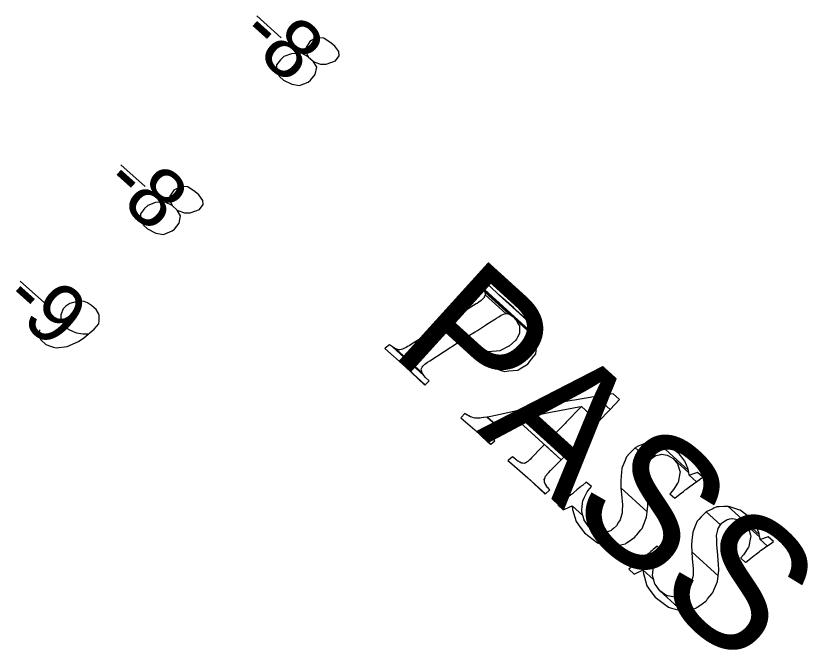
# Model space of a CAD drawing. Extents: x 3962991 to 3983549, y 181631 to 204078.
# Drawn here: x 3976572.4 to 3977019.6, y 191060.4 to 191418 of the extents above; entities that cross this region are included whole.
import ezdxf

# ---------------------------------------------------------------- set-up
doc = ezdxf.new("R2010")
doc.units = 0
for name, color, linetype in [('V-ANNO-MASK', 7, 'Continuous'), ('V-ANNO-MASK2', 7, 'Continuous'), ('V-RIVR-IDEN', 7, 'Continuous'), ('V-RIVR-RANG', 7, 'Continuous')]:
    doc.layers.add(name, color=color, linetype=linetype)

msp = doc.modelspace()

# ---------------------------------------------------------------- linework, layer by layer
at = {"layer": 'V-ANNO-MASK2'}
for p, q in [((3976708.04, 191417.99), (3976721.79, 191405.66)), ((3976631.45, 191334.22), (3976645.2, 191321.9)), ((3976574.79, 191268.71), (3976588.54, 191256.38))]:
    msp.add_line(p, q, dxfattribs=at)
for points in [[(3976736.95, 191394.91), (3976739.7, 191392.45), (3976740.67, 191391.94), (3976743.9, 191390.81), (3976747.08, 191390.8), (3976752.39, 191392.77), (3976754.48, 191395.5), (3976754.16, 191397.91), (3976751.94, 191400.96), (3976749.98, 191402.72), (3976745.72, 191405.48), (3976743.09, 191405.71), (3976740.15, 191404.8), (3976737.97, 191403.56), (3976735.73, 191400.26), (3976735.46, 191398.38), (3976736.95, 191394.91), (3976733.11, 191396.94), (3976727.52, 191396.64), (3976723.31, 191395.1), (3976721.35, 191393.31), (3976719.08, 191390.38), (3976719.09, 191386.83), (3976720.74, 191383.94), (3976723.1, 191381.82), (3976727.71, 191379.46), (3976732.05, 191378.76), (3976736.98, 191380.72), (3976738.24, 191381.72), (3976740.86, 191385.04), (3976741.75, 191389.2), (3976739.7, 191392.45)], [(3976660.36, 191311.15), (3976663.11, 191308.68), (3976664.07, 191308.17), (3976667.31, 191307.04), (3976670.48, 191307.03), (3976675.79, 191309), (3976677.88, 191311.73), (3976677.56, 191314.14), (3976675.34, 191317.2), (3976673.38, 191318.96), (3976669.12, 191321.71), (3976666.49, 191321.94), (3976663.55, 191321.04), (3976661.38, 191319.8), (3976659.13, 191316.5), (3976658.86, 191314.61), (3976660.36, 191311.15), (3976656.51, 191313.18), (3976650.92, 191312.87), (3976646.71, 191311.33), (3976644.75, 191309.55), (3976642.48, 191306.62), (3976642.49, 191303.07), (3976644.14, 191300.17), (3976646.5, 191298.06), (3976651.11, 191295.7), (3976655.45, 191295), (3976660.39, 191296.95), (3976661.64, 191297.95), (3976664.26, 191301.27), (3976665.15, 191305.43), (3976663.11, 191308.68)], [(3976585.63, 191241.28), (3976585.27, 191237.71), (3976586.51, 191235.54), (3976589.26, 191233.07), (3976591.93, 191232.1), (3976593.46, 191231.44), (3976594.97, 191231.14), (3976601.28, 191231.86), (3976607.67, 191234.64), (3976610.54, 191236.67), (3976616.43, 191241.66), (3976619.08, 191244.61), (3976619.35, 191246.49), (3976619.18, 191249.47), (3976618.95, 191250.39), (3976617.51, 191252.74), (3976614.96, 191255.03), (3976612.64, 191256.4), (3976610.91, 191257.24), (3976607.54, 191257.42), (3976602.76, 191256.04), (3976600.41, 191254.61), (3976599, 191253.03), (3976597.69, 191249.6), (3976597.6, 191247.91), (3976598.27, 191245.9), (3976600.1, 191243.19), (3976601.87, 191241.61), (3976604.56, 191240.26), (3976606.46, 191239.62), (3976610.22, 191239.08), (3976612.28, 191239), (3976613.4, 191239.07)]]:
    msp.add_lwpolyline(points, dxfattribs=at)
for points in [[(3976834.16, 191269.19), (3976832.05, 191267.69), (3976865.53, 191237.34), (3976863.46, 191242.62), (3976859.91, 191246.85), (3976844.27, 191261.03), (3976839.3, 191265.75), (3976839.29, 191265.76), (3976835.04, 191269.8), (3976834.92, 191269.72), (3976834.79, 191269.63)], [(3976833.45, 191266.43), (3976835.18, 191264.52), (3976865.73, 191236.81), (3976865.53, 191237.34)], [(3976836.2, 191262.85), (3976836.42, 191262.5), (3976850.09, 191250.11), (3976850.32, 191250.05), (3976850.5, 191249.92), (3976850.85, 191249.67), (3976852.09, 191248.75), (3976865.99, 191236.15), (3976865.73, 191236.81), (3976835.17, 191264.52), (3976835.78, 191263.55), (3976836.07, 191263.06), (3976836.16, 191262.92)], [(3976787.99, 191229.9), (3976786.21, 191230.57), (3976801.18, 191217), (3976800.76, 191218.33), (3976800.53, 191219.06), (3976801.19, 191220.23), (3976801.19, 191220.24), (3976801.55, 191220.86), (3976802.66, 191221.88), (3976803.29, 191222.44), (3976804.05, 191222.95), (3976805.42, 191223.88), (3976821.52, 191234.35), (3976821.8, 191234.53), (3976830.47, 191226.67), (3976837.65, 191221.23), (3976846.25, 191218.24), (3976825.76, 191236.83), (3976825.87, 191236.91), (3976826.17, 191237.1), (3976827.82, 191238.15), (3976831.02, 191240.19), (3976832.2, 191240.93), (3976836.85, 191243.89), (3976836.99, 191243.98), (3976841.45, 191246.81), (3976841.91, 191247.1), (3976842.96, 191247.77), (3976844.31, 191248.63), (3976845.13, 191249.15), (3976845.67, 191249.49), (3976846.51, 191249.86), (3976846.83, 191249.99), (3976848.28, 191250.4), (3976836.65, 191260.94), (3976836.11, 191259.72), (3976835.98, 191259.41), (3976835.39, 191258.81), (3976834.96, 191258.37), (3976834.31, 191257.7), (3976833.01, 191256.79), (3976832.01, 191256.07), (3976831.54, 191255.79), (3976827.05, 191252.99), (3976826.91, 191252.9), (3976822.21, 191249.99), (3976821.02, 191249.25), (3976817.79, 191247.25), (3976816.13, 191246.21), (3976815.82, 191246.02), (3976815.7, 191245.94), (3976812.55, 191243.99), (3976811.85, 191243.55), (3976811.57, 191243.38), (3976795.17, 191233.18), (3976793.75, 191232.29), (3976792.94, 191231.82), (3976792.19, 191231.38), (3976790.74, 191230.66), (3976790.07, 191230.32), (3976788.46, 191230)], [(3976836.59, 191261.37), (3976836.66, 191260.94), (3976848.28, 191250.4), (3976848.6, 191250.48), (3976850.09, 191250.11), (3976836.41, 191262.51)], [(3976852.56, 191253.73), (3976844.27, 191261.03), (3976859.91, 191246.85), (3976859.16, 191247.75), (3976853.75, 191252.68), (3976853.74, 191252.69)], [(3976831.77, 191231.56), (3976825.76, 191236.83), (3976846.25, 191218.24), (3976846.58, 191218.13), (3976847.41, 191217.84), (3976849.96, 191218.07), (3976854.92, 191218.51), (3976856.1, 191219.26), (3976860.81, 191222.17), (3976860.9, 191222.3), (3976864.02, 191226.34), (3976864.33, 191226.76), (3976865.07, 191227.72), (3976865.32, 191229.58), (3976865.48, 191230.7), (3976865.58, 191231.43), (3976865.71, 191232.44), (3976865.77, 191232.83), (3976865.97, 191234.36), (3976866.02, 191234.68), (3976866.14, 191235.56), (3976866.16, 191235.69), (3976866.16, 191235.72), (3976866.13, 191235.81), (3976854.05, 191246.77), (3976854.12, 191246.64), (3976854.15, 191246.58), (3976854.33, 191246.26), (3976855.43, 191244.28), (3976855.85, 191243.53), (3976855.9, 191241.77), (3976855.91, 191241.33), (3976855.95, 191240.16), (3976855.98, 191239.31), (3976855.52, 191238.46), (3976854.77, 191237.06), (3976854.18, 191235.97), (3976853.93, 191235.49), (3976850.12, 191232.07), (3976849.97, 191232), (3976844.81, 191229.49), (3976843.01, 191229.32), (3976838.12, 191228.81), (3976832.74, 191231.14)], [(3976852.09, 191248.75), (3976854.05, 191246.76), (3976866.12, 191235.82), (3976865.99, 191236.15)], [(3976780.3, 191230.83), (3976780.04, 191230.64), (3976791.59, 191220.6), (3976802.87, 191210.37), (3976805.1, 191212.46), (3976803.04, 191214.48), (3976802.15, 191215.59), (3976784.39, 191231.69), (3976782.8, 191232.83), (3976782.71, 191232.75)], [(3976821.79, 191234.54), (3976827.59, 191228.84), (3976830.47, 191226.67)], [(3976785.46, 191231.03), (3976784.4, 191231.69), (3976802.15, 191215.59), (3976801.27, 191216.7), (3976801.18, 191217), (3976786.2, 191230.58)], [(3976791.59, 191220.6), (3976802.64, 191210.15), (3976802.87, 191210.37)], [(3976908.66, 191205.25), (3976898.86, 191203.67), (3976906.9, 191196.39), (3976912.3, 191201.95)], [(3976839.73, 191192.5), (3976837.77, 191192.09), (3976842.42, 191187.88), (3976844.15, 191188.49), (3976849.23, 191189.84), (3976850.14, 191190.05), (3976854.21, 191191), (3976879.41, 191168.14), (3976882.87, 191171.7), (3976860.18, 191192.27), (3976862.14, 191192.67), (3976874.34, 191195.14), (3976875.39, 191195.32), (3976889.43, 191197.84), (3976889.42, 191197.85), (3976890.79, 191198.08), (3976900.22, 191189.53), (3976906.9, 191196.39), (3976898.86, 191203.68), (3976886.84, 191201.66), (3976885.47, 191201.42), (3976871.41, 191198.93), (3976870.37, 191198.74), (3976858.05, 191196.38), (3976856.1, 191195.97), (3976850.13, 191194.69), (3976846.01, 191193.8), (3976845.07, 191193.61)], [(3976874.58, 191181.39), (3976873.46, 191180.23), (3976882.87, 191171.7), (3976883.99, 191172.86), (3976890.99, 191180.05), (3976891.58, 191180.65), (3976899.46, 191188.75), (3976900.22, 191189.53), (3976890.79, 191198.08), (3976890.02, 191197.3), (3976882.16, 191189.19), (3976881.57, 191188.59)], [(3976823.11, 191191.89), (3976822.97, 191191.74), (3976830.74, 191184.98), (3976839.74, 191176.82), (3976842.13, 191178.69), (3976841.65, 191179.23), (3976841.16, 191179.76), (3976840.58, 191180.47), (3976840.49, 191180.58), (3976840.3, 191180.82), (3976839.72, 191181.52), (3976839.65, 191181.65), (3976839.26, 191182.37), (3976839.23, 191182.43), (3976838.74, 191183.33), (3976838.72, 191183.39), (3976838.68, 191184), (3976838.65, 191184.49), (3976838.63, 191184.85), (3976838.78, 191185.11), (3976839.1, 191185.64), (3976839.42, 191186.18), (3976839.48, 191186.26), (3976839.96, 191186.62), (3976840.77, 191187.23), (3976840.9, 191187.32), (3976842.18, 191187.79), (3976842.42, 191187.88), (3976837.77, 191192.1), (3976837.48, 191192.05), (3976835.93, 191191.83), (3976835.73, 191191.8), (3976834.45, 191191.61), (3976833.69, 191191.5), (3976833.57, 191191.49), (3976832.63, 191191.51), (3976831.68, 191191.55), (3976831.22, 191191.56), (3976830.83, 191191.58), (3976830.1, 191191.78), (3976829.16, 191192.05), (3976829.11, 191192.06), (3976828.37, 191192.28), (3976828.29, 191192.31), (3976827.35, 191192.81), (3976827.19, 191192.89), (3976826.71, 191193.14), (3976826.55, 191193.22), (3976826.47, 191193.26), (3976825.8, 191193.69), (3976825.47, 191193.9), (3976825.13, 191194.11)], [(3976837.94, 191178.17), (3976839.54, 191176.65), (3976839.57, 191176.69), (3976839.74, 191176.82), (3976830.73, 191184.98)], [(3976849.43, 191167.68), (3976849.38, 191167.64), (3976851.61, 191165.71), (3976853.11, 191164.41), (3976860.59, 191157.94), (3976870.55, 191148.91), (3976872.73, 191150.95), (3976872.78, 191150.99), (3976872.83, 191151.04), (3976872.93, 191151.13), (3976872.95, 191151.14), (3976872.66, 191151.47), (3976871.81, 191152.43), (3976871.52, 191152.75), (3976870.94, 191153.64), (3976870.89, 191153.72), (3976870.17, 191154.84), (3976870.16, 191154.88), (3976870.06, 191155.55), (3976869.99, 191156.07), (3976869.93, 191156.46), (3976869.87, 191156.91), (3976870.12, 191157.52), (3976870.36, 191158.13), (3976870.4, 191158.22), (3976870.63, 191158.8), (3976871.26, 191159.58), (3976871.25, 191159.59), (3976871.36, 191159.71), (3976872.12, 191160.64), (3976872.27, 191160.81), (3976873.4, 191161.97), (3976876.48, 191165.13), (3976877.01, 191165.69), (3976879.41, 191168.14), (3976870, 191176.68), (3976867.6, 191174.22), (3976867.07, 191173.66), (3976863.99, 191170.5), (3976862.86, 191169.35), (3976862.71, 191169.18), (3976861.87, 191168.32), (3976861.76, 191168.2), (3976861.01, 191167.53), (3976860.57, 191167.13), (3976860.5, 191167.07), (3976860.05, 191166.65), (3976859.42, 191166.39), (3976859.12, 191166.27), (3976858.87, 191166.16), (3976858.52, 191166.01), (3976857.75, 191166.13), (3976857.71, 191166.13), (3976857.1, 191166.22), (3976857.06, 191166.23), (3976856.12, 191166.72), (3976855.96, 191166.8), (3976855.49, 191167.04), (3976855.18, 191167.26), (3976855.02, 191167.38), (3976854.07, 191168.05), (3976853.61, 191168.38), (3976852.08, 191169.67), (3976849.65, 191167.86), (3976849.47, 191167.72)], [(3976912.95, 191155.99), (3976913.02, 191152.33), (3976927.87, 191138.87), (3976928.26, 191142.1), (3976928.26, 191142.38), (3976928.25, 191142.39), (3976928.19, 191145.17), (3976927.74, 191150.56), (3976927.24, 191156.4), (3976927.12, 191159.8), (3976927.06, 191161.2), (3976927.06, 191161.51), (3976927.55, 191163.89), (3976927.92, 191165.58), (3976929.22, 191167.52), (3976921.08, 191174.9), (3976919.48, 191173.23), (3976918.44, 191172.14), (3976917, 191170.63), (3976916.84, 191170.47), (3976916.15, 191169.75), (3976915.17, 191167.35), (3976913.58, 191163.4), (3976913.17, 191158.8), (3976912.94, 191156.27)], [(3976922.34, 191175.48), (3976921.09, 191174.9), (3976929.22, 191167.52), (3976929.94, 191168.59), (3976930.3, 191168.85), (3976931.81, 191169.9), (3976932.64, 191170.47), (3976934.58, 191170.92), (3976935.6, 191171.13), (3976935.79, 191171.17), (3976939.07, 191170.65), (3976939.16, 191170.63), (3976939.83, 191170.24), (3976942.42, 191168.72), (3976951.32, 191160.65), (3976951.07, 191162.13), (3976933.63, 191177.95), (3976932.3, 191177.89), (3976931.43, 191177.86), (3976931.2, 191177.85), (3976931.14, 191177.84), (3976928.56, 191177.73), (3976928.33, 191177.72), (3976927.13, 191177.67), (3976925.51, 191176.93), (3976924.55, 191176.49), (3976922.78, 191175.67)], [(3976934.48, 191177.67), (3976933.64, 191177.94), (3976951.06, 191162.14), (3976950.97, 191162.71), (3976949.05, 191167.37), (3976947.9, 191168.84), (3976945.86, 191171.46), (3976945.85, 191171.47), (3976940.24, 191175.79), (3976939.5, 191176.03)], [(3976940.74, 191149.1), (3976940.59, 191148.93), (3976943.35, 191146.43), (3976943.53, 191146.57), (3976945.19, 191147.89), (3976946.38, 191148.84), (3976948.22, 191150.3), (3976949.23, 191151.1), (3976949.58, 191151.37), (3976949.57, 191151.37), (3976951, 191152.5), (3976951.82, 191153.08), (3976951.81, 191153.09), (3976953.18, 191154.05), (3976953.89, 191154.55), (3976953.88, 191154.55), (3976954.02, 191154.64), (3976955.54, 191155.72), (3976951.55, 191159.33), (3976951.53, 191159.41), (3976951.5, 191159.66), (3976951.49, 191159.67), (3976951.32, 191160.65), (3976942.41, 191168.72), (3976944.99, 191165.56), (3976945.09, 191165.26), (3976945.11, 191165.18), (3976946.2, 191161.73), (3976946.3, 191161.42), (3976946.12, 191160.46), (3976945.77, 191158.57), (3976945.57, 191157.43), (3976945.18, 191155.35), (3976944.95, 191154.99), (3976944.24, 191153.91), (3976942.97, 191151.93), (3976942.15, 191150.65)], [(3976951.6, 191159.35), (3976951.55, 191159.33), (3976955.54, 191155.72), (3976955.58, 191155.75), (3976955.71, 191155.84), (3976957, 191156.76), (3976957.3, 191156.97), (3976959.11, 191158.25), (3976956.14, 191160.94), (3976953.82, 191160.13), (3976953.43, 191159.99), (3976951.77, 191159.41)], [(3976860.59, 191157.94), (3976870.38, 191148.75), (3976870.55, 191148.91)], [(3976879.66, 191144.3), (3976877.54, 191142.66), (3976880.57, 191139.92), (3976883.16, 191141.12), (3976883.81, 191141.43), (3976884.17, 191141.59), (3976884.19, 191141.6), (3976884.18, 191141.6), (3976885.49, 191142.2), (3976891.64, 191136.62), (3976891.3, 191137.85), (3976890.95, 191139.12), (3976891.29, 191142.49), (3976891.33, 191142.83), (3976891.41, 191143.7), (3976891.55, 191144.99), (3976892.62, 191147.12), (3976893.71, 191149.29), (3976894.12, 191150.09), (3976894.59, 191150.7), (3976896.41, 191152.95), (3976893.54, 191155.55), (3976891.32, 191153.67), (3976890.72, 191153.16), (3976890.06, 191152.6), (3976888.26, 191151.07), (3976886.5, 191149.57), (3976885.7, 191148.89), (3976885.12, 191148.46), (3976884.9, 191148.28), (3976882.69, 191146.61), (3976882.13, 191146.17), (3976881.58, 191145.75), (3976880.51, 191144.94), (3976880.49, 191144.92), (3976880.2, 191144.7)], [(3976898.94, 191127.7), (3976895.02, 191130.37), (3976907.44, 191119.11), (3976908.25, 191119.27), (3976908.24, 191119.27), (3976908.68, 191119.36), (3976908.72, 191119.36), (3976911.15, 191119.85), (3976912.01, 191120.02), (3976915.34, 191120.68), (3976915.57, 191120.85), (3976916.16, 191121.26), (3976917.04, 191121.88), (3976918.97, 191123.23), (3976920.95, 191124.59), (3976921.49, 191125.26), (3976921.99, 191125.86), (3976924.33, 191128.68), (3976924.97, 191129.44), (3976925.93, 191131.85), (3976927.51, 191135.79), (3976927.87, 191138.87), (3976913.02, 191152.34), (3976913.34, 191148.64), (3976913.86, 191142.8), (3976913.78, 191139.59), (3976913.74, 191138.27), (3976912.62, 191134.35), (3976912.21, 191133.68), (3976911.75, 191132.93), (3976910.53, 191130.87), (3976908.8, 191129.35), (3976908, 191128.66), (3976907.48, 191128.18), (3976907.18, 191128.09), (3976904.19, 191127.11), (3976903.43, 191126.86), (3976899.67, 191127.57), (3976899.63, 191127.57)], [(3976890.1, 191130.14), (3976892.45, 191126.87), (3976899.9, 191121.25), (3976901.67, 191120.75), (3976901.72, 191120.73), (3976907.44, 191119.11), (3976895.02, 191130.37), (3976893.31, 191132.81), (3976892.37, 191134.15), (3976892.32, 191134.23), (3976891.64, 191136.62), (3976885.49, 191142.2), (3976885.79, 191140.15), (3976885.8, 191140.11), (3976886, 191139.44), (3976886.35, 191138.23), (3976887.79, 191133.37), (3976887.81, 191133.32)], [(3976952.82, 191119.84), (3976952.89, 191116.18), (3976967.74, 191102.71), (3976968.13, 191105.95), (3976968.13, 191106.23), (3976968.12, 191106.24), (3976968.06, 191109.02), (3976967.61, 191114.41), (3976967.11, 191120.25), (3976966.98, 191123.65), (3976966.93, 191125.05), (3976966.92, 191125.36), (3976967.42, 191127.73), (3976967.79, 191129.43), (3976969.09, 191131.37), (3976960.95, 191138.75), (3976959.35, 191137.07), (3976958.31, 191135.99), (3976956.86, 191134.48), (3976956.7, 191134.32), (3976956.02, 191133.6), (3976955.04, 191131.2), (3976953.45, 191127.24), (3976953.03, 191122.65), (3976952.81, 191120.12)], [(3976962.21, 191139.33), (3976960.96, 191138.75), (3976969.09, 191131.37), (3976969.81, 191132.44), (3976970.17, 191132.7), (3976971.68, 191133.75), (3976972.5, 191134.32), (3976974.45, 191134.76), (3976975.46, 191134.98), (3976975.66, 191135.02), (3976978.94, 191134.5), (3976979.03, 191134.48), (3976979.7, 191134.09), (3976982.29, 191132.57), (3976991.19, 191124.5), (3976990.94, 191125.98), (3976973.5, 191141.8), (3976972.17, 191141.74), (3976971.3, 191141.71), (3976971.07, 191141.69), (3976971.01, 191141.69), (3976968.42, 191141.58), (3976968.2, 191141.57), (3976967, 191141.52), (3976965.38, 191140.78), (3976964.41, 191140.34), (3976962.64, 191139.52)], [(3976974.35, 191141.52), (3976973.51, 191141.79), (3976990.93, 191125.99), (3976990.84, 191126.56), (3976988.92, 191131.22), (3976987.77, 191132.69), (3976985.73, 191135.31), (3976985.72, 191135.32), (3976980.11, 191139.63), (3976979.37, 191139.88)], [(3976980.61, 191112.95), (3976980.46, 191112.78), (3976983.22, 191110.28), (3976983.4, 191110.42), (3976985.06, 191111.74), (3976986.25, 191112.69), (3976988.09, 191114.14), (3976989.1, 191114.95), (3976989.45, 191115.22), (3976989.44, 191115.22), (3976990.87, 191116.35), (3976991.69, 191116.93), (3976991.68, 191116.93), (3976993.05, 191117.9), (3976993.76, 191118.4), (3976993.75, 191118.4), (3976993.89, 191118.49), (3976995.41, 191119.57), (3976991.42, 191123.18), (3976991.4, 191123.26), (3976991.37, 191123.51), (3976991.36, 191123.52), (3976991.19, 191124.5), (3976982.28, 191132.57), (3976984.86, 191129.41), (3976984.95, 191129.11), (3976984.97, 191129.03), (3976986.07, 191125.58), (3976986.17, 191125.27), (3976985.99, 191124.31), (3976985.64, 191122.42), (3976985.43, 191121.28), (3976985.05, 191119.2), (3976984.81, 191118.84), (3976984.11, 191117.75), (3976982.84, 191115.78), (3976982.02, 191114.5)], [(3976991.47, 191123.2), (3976991.42, 191123.18), (3976995.41, 191119.57), (3976995.44, 191119.6), (3976995.58, 191119.69), (3976996.87, 191120.61), (3976997.17, 191120.82), (3976998.97, 191122.1), (3976996.01, 191124.79), (3976993.68, 191123.98), (3976993.3, 191123.84), (3976991.64, 191123.26)], [(3976919.53, 191108.14), (3976917.4, 191106.51), (3976920.44, 191103.76), (3976923.03, 191104.97), (3976923.68, 191105.27), (3976924.04, 191105.44), (3976924.06, 191105.45), (3976924.05, 191105.45), (3976925.36, 191106.05), (3976931.51, 191100.47), (3976931.17, 191101.7), (3976930.82, 191102.97), (3976931.16, 191106.34), (3976931.19, 191106.68), (3976931.28, 191107.55), (3976931.42, 191108.84), (3976932.49, 191110.97), (3976933.58, 191113.14), (3976933.98, 191113.94), (3976934.46, 191114.55), (3976936.27, 191116.8), (3976933.41, 191119.39), (3976931.19, 191117.52), (3976930.59, 191117.01), (3976929.93, 191116.45), (3976928.13, 191114.92), (3976926.37, 191113.42), (3976925.56, 191112.74), (3976924.99, 191112.31), (3976924.77, 191112.13), (3976922.56, 191110.46), (3976922, 191110.02), (3976921.45, 191109.6), (3976920.37, 191108.79), (3976920.36, 191108.77), (3976920.06, 191108.55)], [(3976938.81, 191091.55), (3976934.88, 191094.22), (3976947.31, 191082.96), (3976948.11, 191083.12), (3976948.11, 191083.12), (3976948.55, 191083.21), (3976948.58, 191083.21), (3976951.02, 191083.7), (3976951.88, 191083.87), (3976955.21, 191084.53), (3976955.44, 191084.7), (3976956.03, 191085.11), (3976956.91, 191085.73), (3976958.84, 191087.07), (3976960.81, 191088.44), (3976961.36, 191089.11), (3976961.85, 191089.71), (3976964.19, 191092.53), (3976964.84, 191093.29), (3976965.8, 191095.7), (3976967.38, 191099.64), (3976967.74, 191102.71), (3976952.88, 191116.19), (3976953.21, 191112.49), (3976953.73, 191106.65), (3976953.64, 191103.44), (3976953.61, 191102.12), (3976952.48, 191098.2), (3976952.08, 191097.53), (3976951.62, 191096.78), (3976950.4, 191094.72), (3976948.67, 191093.2), (3976947.87, 191092.51), (3976947.35, 191092.03), (3976947.05, 191091.94), (3976944.06, 191090.96), (3976943.29, 191090.71), (3976939.53, 191091.42), (3976939.49, 191091.42)], [(3976929.96, 191093.99), (3976932.32, 191090.72), (3976939.77, 191085.1), (3976941.54, 191084.6), (3976941.59, 191084.58), (3976947.31, 191082.96), (3976934.88, 191094.22), (3976933.18, 191096.66), (3976932.24, 191098), (3976932.19, 191098.08), (3976931.51, 191100.47), (3976925.36, 191106.05), (3976925.66, 191104), (3976925.67, 191103.96), (3976925.86, 191103.29), (3976926.22, 191102.08), (3976927.66, 191097.21), (3976927.68, 191097.17)]]:
    msp.add_lwpolyline(points, close=True, dxfattribs=at)

# ---------------------------------------------------------------- texts
at = {"layer": 'V-ANNO-MASK'}
for s, height, rotation, p in [('-8', 33.5, 318.1331, (3976696.78, 191405.41)), ('-8', 33.5, 318.1331, (3976620.18, 191321.65)), ('PASS', 75, 317.7998, (3976781.92, 191229.36)), ('-9', 33.5, 318.1331, (3976563.53, 191256.14))]:
    msp.add_text(s, height=height, rotation=rotation, dxfattribs=at).set_placement(p)
at = {"layer": 'V-RIVR-IDEN'}
msp.add_text('PASS', height=75, rotation=317.7998, dxfattribs=at).set_placement((3976781.92, 191229.36))
at = {"layer": 'V-RIVR-RANG'}
for s, p in [('-8', (3976696.78, 191405.41)), ('-8', (3976620.18, 191321.65)), ('-9', (3976563.53, 191256.14))]:
    msp.add_text(s, height=33.5, rotation=318.1331, dxfattribs=at).set_placement(p)

doc.saveas('drawing.dxf')
